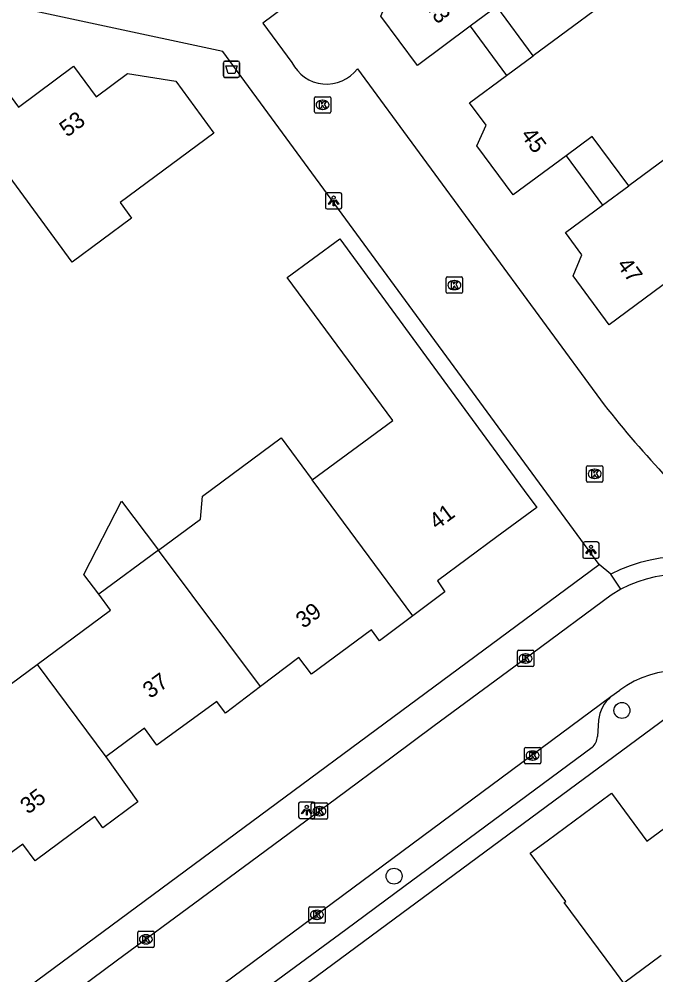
# Model space of a CAD drawing. Extents: x 163427 to 164190, y 380331 to 381641.
# Drawn here: x 163779.2 to 163818.3, y 381325.9 to 381384.4 of the extents above; entities that cross this region are included whole.
import ezdxf

# ---------------------------------------------------------------- set-up
doc = ezdxf.new("R2010")
doc.units = 0
for name, color, linetype in [('IMGEO_Afvalbak', 7, 'Continuous'), ('IMGEO_Boom', 7, 'Continuous'), ('IMGEO_Kolk', 7, 'Continuous'), ('IMGEO_Lichtpunt', 7, 'Continuous'), ('IMGEO_Pand', 7, 'Continuous'), ('IMGEO_Pand_nummerreeks', 7, 'Continuous'), ('IMGEO_Pand_overbouw', 7, 'Continuous'), ('IMGEO_Rijbaan_lokaal_open', 7, 'Continuous'), ('IMGEO_Voetpad_open', 7, 'Continuous')]:
    doc.layers.add(name, color=color, linetype=linetype)

msp = doc.modelspace()

# ---------------------------------------------------------------- linework, layer by layer
at = {"layer": 'IMGEO_Afvalbak'}
for p, q in [((163791.748, 381380.93), (163791.748, 381381.73)), ((163791.748, 381381.73), (163791.748, 381380.93)), ((163791.848, 381381.83), (163792.638, 381381.83)), ((163792.638, 381381.83), (163791.848, 381381.83)), ((163792.738, 381381.73), (163792.738, 381380.93)), ((163792.738, 381380.93), (163792.738, 381381.73)), ((163792.638, 381380.83), (163791.848, 381380.83)), ((163791.848, 381380.83), (163792.638, 381380.83))]:
    msp.add_line(p, q, dxfattribs=at)
msp.add_lwpolyline([(163791.891, 381381.544), (163792.595, 381381.544), (163792.446, 381381.074), (163792.04, 381381.074), (163791.891, 381381.544)], dxfattribs=at)
for centre, start, end in [((163791.848, 381381.73), 90, 180), ((163791.848, 381381.73), 90, 180), ((163792.638, 381381.73), 0, 90), ((163792.638, 381381.73), 360, 90), ((163791.848, 381380.93), 180, 270), ((163791.848, 381380.93), 180, 270), ((163792.638, 381380.93), 270, 0), ((163792.638, 381380.93), 270, 0)]:
    msp.add_arc(centre, 0.1, start, end, dxfattribs=at)
at = {"layer": 'IMGEO_Boom'}
for centre in [(163816.183, 381342.055), (163802.212, 381331.904)]:
    msp.add_circle(centre, 0.489, dxfattribs=at)
at = {"layer": 'IMGEO_Kolk'}
for p, q in [((163797.329, 381378.725), (163797.329, 381379.577)), ((163797.404, 381379.651), (163798.256, 381379.651)), ((163797.817, 381379.431), (163797.842, 381379.431)), ((163798.33, 381379.577), (163798.33, 381378.725)), ((163798.256, 381378.651), (163797.404, 381378.651)), ((163797.84, 381378.871), (163797.815, 381378.871)), ((163805.407, 381367.685), (163805.407, 381368.537)), ((163805.482, 381368.611), (163806.334, 381368.611)), ((163805.895, 381368.391), (163805.92, 381368.391)), ((163806.408, 381368.537), (163806.408, 381367.685)), ((163806.334, 381367.611), (163805.482, 381367.611)), ((163805.918, 381367.831), (163805.893, 381367.831)), ((163814.009, 381356.121), (163814.009, 381356.973)), ((163814.084, 381357.047), (163814.936, 381357.047)), ((163815.01, 381356.973), (163815.01, 381356.121)), ((163814.497, 381356.827), (163814.522, 381356.827)), ((163814.936, 381356.047), (163814.084, 381356.047)), ((163814.52, 381356.267), (163814.495, 381356.267)), ((163809.775, 381344.815), (163809.775, 381345.667)), ((163809.85, 381345.741), (163810.702, 381345.741)), ((163810.263, 381345.521), (163810.288, 381345.521)), ((163810.776, 381345.667), (163810.776, 381344.815)), ((163810.702, 381344.741), (163809.85, 381344.741)), ((163810.286, 381344.961), (163810.261, 381344.961)), ((163810.206, 381338.865), (163810.206, 381339.717)), ((163810.281, 381339.791), (163811.133, 381339.791)), ((163810.694, 381339.571), (163810.719, 381339.571)), ((163811.207, 381339.717), (163811.207, 381338.865)), ((163811.133, 381338.791), (163810.281, 381338.791)), ((163810.717, 381339.011), (163810.692, 381339.011)), ((163797.135, 381335.464), (163797.135, 381336.316)), ((163797.21, 381336.39), (163798.062, 381336.39)), ((163797.623, 381336.17), (163797.648, 381336.17)), ((163798.136, 381336.316), (163798.136, 381335.464)), ((163798.062, 381335.39), (163797.21, 381335.39)), ((163797.646, 381335.61), (163797.621, 381335.61)), ((163797.056, 381330.032), (163797.908, 381330.032)), ((163796.981, 381329.106), (163796.981, 381329.958)), ((163797.469, 381329.812), (163797.494, 381329.812)), ((163797.982, 381329.958), (163797.982, 381329.106)), ((163797.908, 381329.032), (163797.056, 381329.032)), ((163797.492, 381329.252), (163797.467, 381329.252)), ((163786.5, 381327.608), (163786.5, 381328.46)), ((163786.575, 381328.534), (163787.427, 381328.534)), ((163786.988, 381328.314), (163787.013, 381328.314)), ((163787.501, 381328.46), (163787.501, 381327.608)), ((163787.011, 381327.754), (163786.986, 381327.754)), ((163787.427, 381327.534), (163786.575, 381327.534))]:
    msp.add_line(p, q, dxfattribs=at)
for points in [[(163797.329, 381378.725), (163797.329, 381379.577)], [(163797.404, 381379.651), (163798.256, 381379.651)], [(163797.65, 381379.351), (163797.773, 381379.351), (163797.773, 381379.2), (163797.903, 381379.351), (163798.067, 381379.351), (163797.921, 381379.2), (163798.074, 381378.951), (163797.922, 381378.951), (163797.837, 381379.115), (163797.773, 381379.048), (163797.773, 381378.951), (163797.65, 381378.951), (163797.65, 381379.351)], [(163798.33, 381379.577), (163798.33, 381378.725)], [(163798.256, 381378.651), (163797.404, 381378.651)], [(163805.407, 381367.685), (163805.407, 381368.537)], [(163805.482, 381368.611), (163806.334, 381368.611)], [(163805.728, 381368.311), (163805.851, 381368.311), (163805.851, 381368.16), (163805.981, 381368.311), (163806.145, 381368.311), (163805.999, 381368.16), (163806.152, 381367.911), (163806, 381367.911), (163805.915, 381368.075), (163805.851, 381368.008), (163805.851, 381367.911), (163805.728, 381367.911), (163805.728, 381368.311)], [(163806.408, 381368.537), (163806.408, 381367.685)], [(163806.334, 381367.611), (163805.482, 381367.611)], [(163814.009, 381356.121), (163814.009, 381356.973)], [(163814.084, 381357.047), (163814.936, 381357.047)], [(163815.01, 381356.973), (163815.01, 381356.121)], [(163814.33, 381356.747), (163814.453, 381356.747), (163814.453, 381356.596), (163814.583, 381356.747), (163814.747, 381356.747), (163814.601, 381356.596), (163814.754, 381356.347), (163814.602, 381356.347), (163814.517, 381356.511), (163814.453, 381356.444), (163814.453, 381356.347), (163814.33, 381356.347), (163814.33, 381356.747)], [(163814.936, 381356.047), (163814.084, 381356.047)], [(163809.775, 381344.815), (163809.775, 381345.667)], [(163809.85, 381345.741), (163810.702, 381345.741)], [(163810.096, 381345.441), (163810.219, 381345.441), (163810.219, 381345.29), (163810.349, 381345.441), (163810.513, 381345.441), (163810.367, 381345.29), (163810.52, 381345.041), (163810.368, 381345.041), (163810.283, 381345.205), (163810.219, 381345.138), (163810.219, 381345.041), (163810.096, 381345.041), (163810.096, 381345.441)], [(163810.776, 381345.667), (163810.776, 381344.815)], [(163810.702, 381344.741), (163809.85, 381344.741)], [(163810.206, 381338.865), (163810.206, 381339.717)], [(163810.281, 381339.791), (163811.133, 381339.791)], [(163810.527, 381339.491), (163810.65, 381339.491), (163810.65, 381339.34), (163810.78, 381339.491), (163810.944, 381339.491), (163810.798, 381339.34), (163810.951, 381339.091), (163810.799, 381339.091), (163810.714, 381339.255), (163810.65, 381339.188), (163810.65, 381339.091), (163810.527, 381339.091), (163810.527, 381339.491)], [(163811.207, 381339.717), (163811.207, 381338.865)], [(163811.133, 381338.791), (163810.281, 381338.791)], [(163797.135, 381335.464), (163797.135, 381336.316)], [(163797.21, 381336.39), (163798.062, 381336.39)], [(163797.456, 381336.09), (163797.579, 381336.09), (163797.579, 381335.939), (163797.709, 381336.09), (163797.873, 381336.09), (163797.727, 381335.939), (163797.88, 381335.69), (163797.728, 381335.69), (163797.643, 381335.854), (163797.579, 381335.787), (163797.579, 381335.69), (163797.456, 381335.69), (163797.456, 381336.09)], [(163798.136, 381336.316), (163798.136, 381335.464)], [(163798.062, 381335.39), (163797.21, 381335.39)], [(163797.056, 381330.032), (163797.908, 381330.032)], [(163796.981, 381329.106), (163796.981, 381329.958)], [(163797.302, 381329.732), (163797.425, 381329.732), (163797.425, 381329.581), (163797.555, 381329.732), (163797.719, 381329.732), (163797.573, 381329.581), (163797.726, 381329.332), (163797.574, 381329.332), (163797.489, 381329.496), (163797.425, 381329.429), (163797.425, 381329.332), (163797.302, 381329.332), (163797.302, 381329.732)], [(163797.982, 381329.958), (163797.982, 381329.106)], [(163797.908, 381329.032), (163797.056, 381329.032)], [(163786.5, 381327.608), (163786.5, 381328.46)], [(163786.575, 381328.534), (163787.427, 381328.534)], [(163786.821, 381328.234), (163786.944, 381328.234), (163786.944, 381328.083), (163787.074, 381328.234), (163787.238, 381328.234), (163787.092, 381328.083), (163787.245, 381327.834), (163787.093, 381327.834), (163787.008, 381327.998), (163786.944, 381327.931), (163786.944, 381327.834), (163786.821, 381327.834), (163786.821, 381328.234)], [(163787.501, 381328.46), (163787.501, 381327.608)], [(163787.427, 381327.534), (163786.575, 381327.534)]]:
    msp.add_lwpolyline(points, dxfattribs=at)
for centre, start, end in [((163797.406, 381379.575), 91.55205, 178.44795), ((163797.406, 381379.575), 91.55205, 178.44795), ((163798.254, 381379.575), 1.55205, 88.44795), ((163798.254, 381379.575), 1.55205, 88.44795), ((163797.406, 381378.727), 181.55205, 268.44795), ((163797.406, 381378.727), 181.55205, 268.44795), ((163798.254, 381378.727), 271.55205, 358.44795), ((163798.254, 381378.727), 271.55205, 358.44795), ((163805.484, 381368.535), 91.55205, 178.44795), ((163805.484, 381368.535), 91.55205, 178.44795), ((163806.332, 381368.535), 1.55205, 88.44795), ((163806.332, 381368.535), 1.55205, 88.44795), ((163805.484, 381367.687), 181.55205, 268.44795), ((163805.484, 381367.687), 181.55205, 268.44795), ((163806.332, 381367.687), 271.55205, 358.44795), ((163806.332, 381367.687), 271.55205, 358.44795), ((163814.086, 381356.971), 91.55205, 178.44795), ((163814.086, 381356.971), 91.55205, 178.44795), ((163814.934, 381356.971), 1.55205, 88.44795), ((163814.934, 381356.971), 1.55205, 88.44795), ((163814.086, 381356.123), 181.55205, 268.44795), ((163814.086, 381356.123), 181.55205, 268.44795), ((163814.934, 381356.123), 271.55205, 358.44795), ((163814.934, 381356.123), 271.55205, 358.44795), ((163809.852, 381345.665), 91.55205, 178.44795), ((163809.852, 381345.665), 91.55205, 178.44795), ((163810.7, 381345.665), 1.55205, 88.44795), ((163810.7, 381345.665), 1.55205, 88.44795), ((163809.852, 381344.817), 181.55205, 268.44795), ((163809.852, 381344.817), 181.55205, 268.44795), ((163810.7, 381344.817), 271.55205, 358.44795), ((163810.7, 381344.817), 271.55205, 358.44795), ((163810.283, 381339.715), 91.55205, 178.44795), ((163810.283, 381339.715), 91.55205, 178.44795), ((163811.131, 381339.715), 1.55205, 88.44795), ((163811.131, 381339.715), 1.55205, 88.44795), ((163810.283, 381338.867), 181.55205, 268.44795), ((163810.283, 381338.867), 181.55205, 268.44795), ((163811.131, 381338.867), 271.55205, 358.44795), ((163811.131, 381338.867), 271.55205, 358.44795), ((163797.212, 381336.314), 91.55205, 178.44795), ((163797.212, 381336.314), 91.55205, 178.44795), ((163798.06, 381336.314), 1.55205, 88.44795), ((163798.06, 381336.314), 1.55205, 88.44795), ((163797.212, 381335.466), 181.55205, 268.44795), ((163797.212, 381335.466), 181.55205, 268.44795), ((163798.06, 381335.466), 271.55205, 358.44795), ((163798.06, 381335.466), 271.55205, 358.44795), ((163797.058, 381329.956), 91.55205, 178.44795), ((163797.058, 381329.956), 91.55205, 178.44795), ((163797.906, 381329.956), 1.55205, 88.44795), ((163797.906, 381329.956), 1.55205, 88.44795), ((163797.058, 381329.108), 181.55205, 268.44795), ((163797.058, 381329.108), 181.55205, 268.44795), ((163797.906, 381329.108), 271.55205, 358.44795), ((163797.906, 381329.108), 271.55205, 358.44795), ((163786.577, 381328.458), 91.55205, 178.44795), ((163786.577, 381328.458), 91.55205, 178.44795), ((163787.425, 381328.458), 1.55205, 88.44795), ((163787.425, 381328.458), 1.55205, 88.44795), ((163786.577, 381327.61), 181.55205, 268.44795), ((163786.577, 381327.61), 181.55205, 268.44795), ((163787.425, 381327.61), 271.55205, 358.44795), ((163787.425, 381327.61), 271.55205, 358.44795)]:
    msp.add_arc(centre, 0.0765, start, end, dxfattribs=at)
for centre, major_axis, ratio, start_param, end_param in [((163797.816, 381379.151), (-0.387, 0.002), 0.722429, 4.712389, 7.853982), ((163797.841, 381379.151), (-0.39, 0.002), 0.717154, 1.570796, 4.712389), ((163805.894, 381368.111), (-0.387, 0.002), 0.722429, 4.712389, 7.853982), ((163805.919, 381368.111), (-0.39, 0.002), 0.717154, 1.570796, 4.712389), ((163814.496, 381356.547), (-0.387, 0.002), 0.722429, 4.712389, 7.853982), ((163814.521, 381356.547), (-0.39, 0.002), 0.717154, 1.570796, 4.712389), ((163810.262, 381345.241), (-0.387, 0.002), 0.722429, 4.712389, 7.853982), ((163810.287, 381345.241), (-0.39, 0.002), 0.717154, 1.570796, 4.712389), ((163810.693, 381339.291), (-0.387, 0.002), 0.722429, 4.712389, 7.853982), ((163810.718, 381339.291), (-0.39, 0.002), 0.717154, 1.570796, 4.712389), ((163797.622, 381335.89), (-0.387, 0.002), 0.722429, 4.712389, 7.853982), ((163797.647, 381335.89), (-0.39, 0.002), 0.717154, 1.570796, 4.712389), ((163797.468, 381329.532), (-0.387, 0.002), 0.722429, 4.712389, 7.853982), ((163797.493, 381329.532), (-0.39, 0.002), 0.717154, 1.570796, 4.712389), ((163786.987, 381328.034), (-0.387, 0.002), 0.722429, 4.712389, 7.853982), ((163787.012, 381328.034), (-0.39, 0.002), 0.717154, 1.570796, 4.712389)]:
    msp.add_ellipse(centre, major_axis=major_axis, ratio=ratio, start_param=start_param, end_param=end_param, dxfattribs=at)
at = {"layer": 'IMGEO_Lichtpunt'}
for p, q in [((163798.011, 381373.676), (163798.011, 381372.869)), ((163798.011, 381373.676), (163798.011, 381372.869)), ((163798.913, 381373.771), (163798.105, 381373.771)), ((163798.913, 381373.771), (163798.105, 381373.771)), ((163799.007, 381372.869), (163799.007, 381373.676)), ((163799.007, 381372.869), (163799.007, 381373.676)), ((163798.105, 381372.775), (163798.913, 381372.775)), ((163798.105, 381372.775), (163798.913, 381372.775)), ((163813.784, 381352.279), (163813.784, 381351.472)), ((163813.784, 381352.279), (163813.784, 381351.472)), ((163814.686, 381352.374), (163813.878, 381352.374)), ((163814.686, 381352.374), (163813.878, 381352.374)), ((163814.78, 381351.472), (163814.78, 381352.279)), ((163814.78, 381351.472), (163814.78, 381352.279)), ((163813.878, 381351.378), (163814.686, 381351.378)), ((163813.878, 381351.378), (163814.686, 381351.378)), ((163797.261, 381336.442), (163796.453, 381336.442)), ((163797.261, 381336.442), (163796.453, 381336.442)), ((163796.359, 381336.347), (163796.359, 381335.54)), ((163796.359, 381336.347), (163796.359, 381335.54)), ((163797.355, 381335.54), (163797.355, 381336.347)), ((163797.355, 381335.54), (163797.355, 381336.347)), ((163796.453, 381335.446), (163797.261, 381335.446)), ((163796.453, 381335.446), (163797.261, 381335.446))]:
    msp.add_line(p, q, dxfattribs=at)
for points in [[(163798.385, 381373.34), (163798.424, 381373.312), (163798.236, 381373.05), (163798.198, 381373.077), (163798.385, 381373.34)], [(163798.597, 381373.312), (163798.635, 381373.339), (163798.822, 381373.077), (163798.783, 381373.049), (163798.597, 381373.312)], [(163798.487, 381373.292), (163798.534, 381373.292), (163798.534, 381372.97), (163798.487, 381372.97), (163798.487, 381373.292)], [(163814.158, 381351.943), (163814.197, 381351.915), (163814.009, 381351.653), (163813.971, 381351.68), (163814.158, 381351.943)], [(163814.26, 381351.895), (163814.307, 381351.895), (163814.307, 381351.573), (163814.26, 381351.573), (163814.26, 381351.895)], [(163814.37, 381351.915), (163814.408, 381351.942), (163814.595, 381351.68), (163814.556, 381351.652), (163814.37, 381351.915)], [(163796.733, 381336.011), (163796.772, 381335.983), (163796.584, 381335.721), (163796.546, 381335.748), (163796.733, 381336.011)], [(163796.835, 381335.963), (163796.882, 381335.963), (163796.882, 381335.641), (163796.835, 381335.641), (163796.835, 381335.963)], [(163796.945, 381335.983), (163796.983, 381336.01), (163797.17, 381335.748), (163797.131, 381335.72), (163796.945, 381335.983)]]:
    msp.add_lwpolyline(points, dxfattribs=at)
for centre in [(163798.51, 381373.474), (163814.283, 381352.077), (163796.858, 381336.145)]:
    msp.add_circle(centre, 0.0994, dxfattribs=at)
for centre, start, end in [((163798.105, 381373.676), 90, 180), ((163798.105, 381373.676), 90, 180), ((163798.913, 381373.676), 0, 90), ((163798.913, 381373.676), 0, 90), ((163798.105, 381372.869), 180, 270), ((163798.105, 381372.869), 180, 270), ((163798.913, 381372.869), 270, 0), ((163798.913, 381372.869), 270, 360), ((163813.878, 381352.279), 90, 180), ((163813.878, 381352.279), 90, 180), ((163814.686, 381352.279), 0, 90), ((163814.686, 381352.279), 0, 90), ((163813.878, 381351.472), 180, 270), ((163813.878, 381351.472), 180, 270), ((163814.686, 381351.472), 270, 0), ((163814.686, 381351.472), 270, 360), ((163796.453, 381336.347), 90, 180), ((163796.453, 381336.347), 90, 180), ((163797.261, 381336.347), 0, 90), ((163797.261, 381336.347), 0, 90), ((163796.453, 381335.54), 180, 270), ((163796.453, 381335.54), 180, 270), ((163797.261, 381335.54), 270, 0), ((163797.261, 381335.54), 270, 360)]:
    msp.add_arc(centre, 0.0946, start, end, dxfattribs=at)
at = {"layer": 'IMGEO_Pand'}
for points in [[(163810.746, 381382.162), (163808.513, 381385.177), (163806.872, 381383.962), (163803.641, 381381.57), (163801.406, 381384.59), (163801.948, 381385.861), (163800.835, 381387.333), (163810.922, 381394.781), (163812.882, 381392.127), (163813.928, 381392.899), (163816.899, 381388.877), (163817.932, 381387.478), (163816.886, 381386.704)], [(163816.886, 381386.704), (163810.746, 381382.162)], [(163774.077, 381380.952), (163776.458, 381382.705), (163779.196, 381379.013), (163782.568, 381381.513), (163783.943, 381379.645), (163785.869, 381381.062), (163788.825, 381380.604), (163791.172, 381377.414), (163787.546, 381374.745), (163785.416, 381373.177), (163786.126, 381372.212), (163782.475, 381369.524), (163778.221, 381375.313)], [(163816.605, 381374.192), (163814.365, 381377.218), (163812.757, 381376.028), (163809.519, 381373.631), (163807.294, 381376.636), (163807.856, 381377.91), (163806.844, 381379.276), (163809.103, 381380.947), (163810.746, 381382.162)], [(163822.766, 381378.742), (163816.605, 381374.192)], [(163822.499, 381366.244), (163820.26, 381369.268), (163818.63, 381368.061), (163815.408, 381365.675), (163813.183, 381368.681), (163813.731, 381369.957), (163812.719, 381371.323), (163814.996, 381373.004), (163816.605, 381374.192)], [(163797.201, 381356.177), (163802.14, 381359.822), (163795.668, 381368.58), (163798.89, 381370.95), (163810.185, 381355.538), (163810.958, 381354.495), (163808.511, 381352.684), (163804.883, 381349.985), (163805.33, 381349.317), (163803.357, 381347.842)], [(163787.763, 381351.87), (163790.339, 381353.777), (163790.461, 381355.18), (163795.302, 381358.751), (163797.201, 381356.177)], [(163803.357, 381347.842), (163797.201, 381356.177)], [(163784.119, 381349.172), (163783.204, 381350.39), (163785.505, 381354.873), (163787.763, 381351.87)], [(163787.763, 381351.87), (163784.119, 381349.172)], [(163794.035, 381343.526), (163787.763, 381351.87)], [(163780.336, 381344.88), (163784.831, 381348.208), (163784.119, 381349.172)], [(163803.357, 381347.842), (163801.326, 381346.324), (163800.821, 381346.997), (163797.152, 381344.268), (163796.365, 381345.298), (163794.035, 381343.526)], [(163772.822, 381337.902), (163777.298, 381341.215), (163776.622, 381342.131), (163780.336, 381344.88)], [(163780.336, 381344.88), (163784.535, 381339.216)], [(163794.035, 381343.526), (163791.884, 381341.89), (163791.349, 381342.598), (163787.668, 381339.924), (163786.906, 381340.961), (163784.535, 381339.216)], [(163784.535, 381339.216), (163786.506, 381336.459), (163784.363, 381334.862), (163783.862, 381335.565), (163780.204, 381332.844), (163779.452, 381333.872), (163777.063, 381332.12)], [(163818.594, 381327.036), (163816.301, 381325.344), (163815.619, 381326.269), (163812.65, 381330.292), (163812.739, 381330.357), (163810.56, 381333.31), (163811.591, 381334.072), (163815.466, 381336.935), (163815.54, 381336.99), (163817.706, 381334.047), (163822.29, 381337.42), (163825.95, 381332.49), (163823.568, 381330.736)]]:
    msp.add_lwpolyline(points, dxfattribs=at)
at = {"layer": 'IMGEO_Pand_overbouw'}
for points in [[(163808.513, 381385.177), (163806.872, 381383.962), (163809.103, 381380.947), (163810.746, 381382.162)], [(163814.365, 381377.218), (163812.757, 381376.028), (163814.996, 381373.004), (163816.605, 381374.192)]]:
    msp.add_lwpolyline(points, close=True, dxfattribs=at)
at = {"layer": 'IMGEO_Rijbaan_lokaal_open'}
for points in [[(163816.123, 381349.488), (163815.525, 381349.108), (163810.719, 381345.57), (163804.679, 381341.117), (163802.094, 381339.2), (163798.678, 381336.67), (163793.429, 381332.783), (163790.393, 381330.532), (163785.174, 381326.696), (163782.151, 381324.455), (163777.032, 381320.682), (163774.005, 381318.419), (163768.769, 381314.563), (163763.335, 381310.52), (163752.679, 381302.631), (163749.656, 381300.386), (163748.711, 381299.272)], [(163756.404, 381299.143), (163815.509, 381342.901)], [(163815.509, 381342.901), (163816.049, 381343.302)]]:
    msp.add_lwpolyline(points, dxfattribs=at)
for centre, radius, start, end in [((163819.761, 381342.607), 7.783, 52.99488, 117.86877), ((163819.796, 381338.133), 6.385, 53.09594, 125.93668)]:
    msp.add_arc(centre, radius, start, end, dxfattribs=at)
at = {"layer": 'IMGEO_Voetpad_open'}
for points in [[(163838.787, 381417.275), (163794.165, 381384.158), (163795.953, 381381.752)], [(163814.795, 381351.002), (163791.71, 381382.427), (163768.213, 381387.455), (163761.832, 381382.67), (163761.181, 381383.573)], [(163799.974, 381381.359), (163815.099, 381360.779)], [(163748.934, 381302.31), (163814.795, 381351.002)], [(163815.506, 381350.4), (163814.795, 381351.002)], [(163816.123, 381349.488), (163815.506, 381350.4)], [(163756.006, 381295.168), (163818.972, 381341.665)], [(163814.749, 381341.459), (163814.675, 381340.46)], [(163814.348, 381339.779), (163802.256, 381330.841), (163799.249, 381328.618), (163794.403, 381325.036), (163791.395, 381322.812), (163786.556, 381319.235), (163783.531, 381317), (163778.698, 381313.427), (163775.665, 381311.185), (163759.558, 381299.279)]]:
    msp.add_lwpolyline(points, dxfattribs=at)
for centre, radius, start, end in [((163798.085, 381382.797), 2.374, 206.11086, 322.72478), ((163860.325, 381395.857), 57.235, 217.79815, 229.61638), ((163819.799, 381342.261), 9.202, 54.53184, 117.80606), ((163816.97, 381341.21), 2.235, 130.82431, 173.59312), ((163813.659, 381340.529), 1.018, 312.56736, 356.13422)]:
    msp.add_arc(centre, radius, start, end, dxfattribs=at)

# ---------------------------------------------------------------- texts
at = {"layer": 'IMGEO_Pand_nummerreeks'}
for s, rotation, p in [('43', 306.50293, (163804.057, 381385.242)), ('53', 36.55471, (163782.171, 381377.135)), ('45', 306.52012, (163809.939, 381377.297)), ('47', 306.50866, (163815.828, 381369.34)), ('41', 36.64689, (163804.836, 381353.09)), ('39', 36.64185, (163796.659, 381347.042)), ('37', 35.99589, (163787.266, 381342.747)), ('35', 36.64368, (163779.767, 381335.66))]:
    msp.add_text(s, height=1, rotation=rotation, dxfattribs=at).set_placement(p)

doc.saveas('drawing.dxf')
